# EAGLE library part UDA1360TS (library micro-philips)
Stereo audio A/D CONVERTER
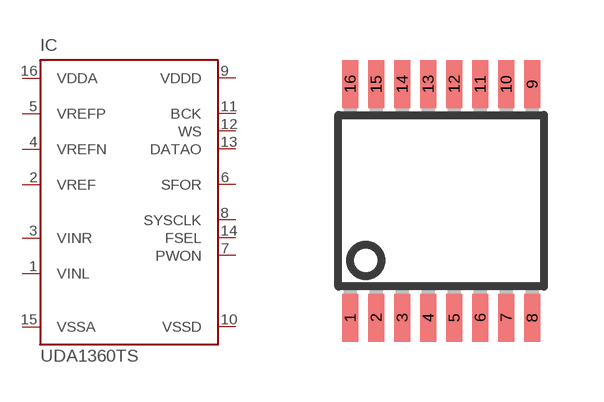
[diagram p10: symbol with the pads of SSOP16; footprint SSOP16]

Designator prefix IC

## UDA1360TS (OC_FARNELL: unknown; OC_NEWARK: unknown)  [SSOP16]
1  VINL  in
2  VREF  in
3  VINR  in
4  VREFN  in
5  VREFP  in
6  SFOR  in
7  PWON  in
8  SYSCLK  in
9  VDDD  pwr
10  VSSD  pwr
11  BCK  in
12  WS  in
13  DATAO  in
14  FSEL  in
15  VSSA  pwr
16  VDDA  pwr

## Footprint SSOP16 (pad centres in mm)
Small Shrink Outline Package
smd 0.4 x 1.2: 1 -2.275,-2.925; 2 -1.625,-2.925; 3 -0.975,-2.925; 4 -0.325,-2.925; 5 0.325,-2.925; 6 0.975,-2.925; 7 1.625,-2.925; 8 2.275,-2.925; 9 2.275,2.925; 10 1.625,2.925; 11 0.975,2.925; 12 0.325,2.925; 13 -0.325,2.925; 14 -0.975,2.925; 15 -1.625,2.925; 16 -2.275,2.925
